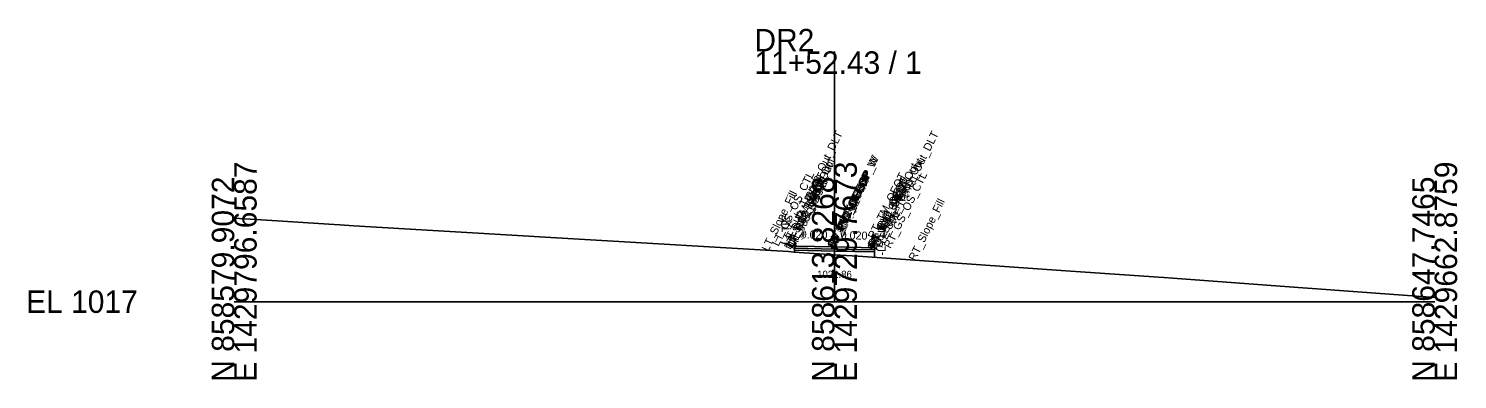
# Model space of a CAD drawing. Extents: x -26 to 1303, y -10 to 3033.
# Drawn here: x 1124.3 to 1302.8, y -9.7 to 34.1 of the extents above; entities that cross this region are included whole.
import ezdxf

# ---------------------------------------------------------------- set-up
doc = ezdxf.new("R2010")
doc.units = 0
for name, color, linetype in [('Exist Cross Section Cell', 7, 'Continuous'), ('Exist XS Center Line Elevation Label', 7, 'Continuous'), ('Exist XS Ground Line', 7, 'Continuous'), ('Prop CMT Pvmt Course 1', 7, 'Continuous'), ('Prop CMT Pvmt Course 2', 7, 'Continuous'), ('Prop CMT Pvmt Surface', 7, 'Continuous'), ('Prop CMT Pvmt Surface Overlay', 7, 'Continuous'), ('Prop CMT Shld Paved Course 1', 7, 'Continuous'), ('Prop CMT Shld Paved Course 2', 7, 'Continuous'), ('Prop CMT Slope Grass', 7, 'Continuous'), ('Prop CMT Subgrade Earthwork', 7, 'Continuous'), ('Prop XS Dump Level', 7, 'Continuous'), ('Prop XS EOT Tick Mark', 7, 'Continuous'), ('Prop XS SE Text', 7, 'Continuous'), ('Prop XSC Text', 7, 'Continuous')]:
    doc.layers.add(name, color=color, linetype=linetype)

msp = doc.modelspace()

# ---------------------------------------------------------------- linework, layer by layer
at = {"layer": 'Exist Cross Section Cell'}
for p, q in [((1225, 0), (1225, 31.22)), ((1150, 0), (1225, 0)), ((1225, 0), (1300, 0))]:
    msp.add_line(p, q, dxfattribs=at)
at = {"layer": 'Exist XS Ground Line'}
msp.add_lwpolyline([(1150, 10.41), (1156.02, 10.05), (1161.84, 9.67), (1163.21, 9.58), (1164.96, 9.46), (1186.81, 8.18), (1188.14, 8.1), (1192.41, 7.84), (1219.26, 6.24), (1219.97, 6.19), (1225, 5.86), (1226.48, 5.76), (1227.95, 5.66), (1253.9, 3.85), (1256.35, 3.67), (1265.5, 3.07), (1266.14, 3.02), (1267.3, 2.93), (1282.94, 1.75), (1284.68, 1.63), (1300, 0.52)], dxfattribs=at)
at = {"layer": 'Prop CMT Pvmt Course 1'}
for points in [[(1225, 6.82), (1220, 6.92)], [(1220, 6.92), (1220, 6.67)], [(1220, 6.67), (1225, 6.57)], [(1225, 6.69), (1225, 6.82)], [(1225, 6.82), (1230, 6.72)], [(1225, 6.69), (1225, 6.82)], [(1225, 6.57), (1225, 6.69), (1225, 6.69)], [(1225, 6.57), (1225, 6.69), (1225, 6.69)], [(1230, 6.47), (1225, 6.57)], [(1230, 6.72), (1230, 6.47)]]:
    msp.add_lwpolyline(points, dxfattribs=at)
at = {"layer": 'Prop CMT Pvmt Course 2'}
for points in [[(1225, 6.57), (1220, 6.67)], [(1220, 6.67), (1220, 6.42)], [(1220, 6.42), (1225, 6.32)], [(1225, 6.32), (1225, 6.57)], [(1225, 6.32), (1225, 6.57)], [(1225, 6.57), (1230, 6.47)], [(1230, 6.22), (1225, 6.32)], [(1230, 6.47), (1230, 6.22)]]:
    msp.add_lwpolyline(points, dxfattribs=at)
at = {"layer": 'Prop CMT Pvmt Surface'}
for points in [[(1225, 6.82), (1220, 6.92)], [(1225, 6.82), (1230, 6.72)]]:
    msp.add_lwpolyline(points, dxfattribs=at)
at = {"layer": 'Prop CMT Pvmt Surface Overlay'}
for points in [[(1225, 6.82), (1220, 6.92)], [(1225, 6.82), (1230, 6.72)]]:
    msp.add_lwpolyline(points, dxfattribs=at)
at = {"layer": 'Prop CMT Shld Paved Course 1'}
for points in [[(1220, 6.67), (1220, 6.92)], [(1230, 6.47), (1230, 6.72)]]:
    msp.add_lwpolyline(points, dxfattribs=at)
at = {"layer": 'Prop CMT Shld Paved Course 2'}
for points in [[(1220, 6.42), (1220, 6.67)], [(1230, 6.22), (1230, 6.47)]]:
    msp.add_lwpolyline(points, dxfattribs=at)
at = {"layer": 'Prop CMT Slope Grass'}
for p, q in [((1220, 6.42), (1220, 6.19)), ((1230, 6.22), (1230, 5.52))]:
    msp.add_line(p, q, dxfattribs=at)
at = {"layer": 'Prop CMT Subgrade Earthwork'}
for q in [(1220, 6.42), (1230, 6.22)]:
    msp.add_line((1225, 6.32), q, dxfattribs=at)
at = {"layer": 'Prop XS EOT Tick Mark'}
for points in [[(1220, 6.92), (1220, 7.92)], [(1230, 6.72), (1230, 7.72)]]:
    msp.add_lwpolyline(points, dxfattribs=at)

# ---------------------------------------------------------------- texts
at = {"layer": 'Exist Cross Section Cell'}
for s, p in [('DR2', (1215, 31.22)), ('11+52.43 / 1', (1215, 28.42)), ('EL 1017', (1124, -1.4))]:
    msp.add_text(s, height=2.8, dxfattribs=at).set_placement(p)
for s, p in [('E 1429796.6587', (1152.8, -10)), ('E 1429729.7673', (1227.8, -10)), ('E 1429662.8759', (1302.8, -10)), ('N 858579.9072', (1150, -10)), ('N 858613.8268', (1225, -10)), ('N 858647.7465', (1300, -10))]:
    msp.add_text(s, height=2.8, rotation=90, dxfattribs=at).set_placement(p)
at = {"layer": 'Exist XS Center Line Elevation Label'}
msp.add_text('1022.86', height=0.9, dxfattribs=at).set_placement((1222.83, 2.96))
at = {"layer": 'Prop XS Dump Level'}
for s, p in [('LT_Sub_Trench_Out_DLT', (1219.06, 6.88)), ('RT_Sub_Trench_Out_DLT', (1230.94, 6.64)), ('LT_Sub_Trench_Out', (1219.51, 6.43)), ('RT_PV1_OEEOP_W', (1225, 6.69)), ('LT_PV1_OEEOP_W', (1225, 6.69)), ('RT_Sub_Trench_Out', (1230.51, 6.21)), ('LT_PS2_Shelf_Out', (1219.75, 6.67)), ('LT_TM_OEOT', (1220, 7.92)), ('RT_PV2_OEEOP', (1225, 6.57)), ('LT_PV2_OEEOP', (1225, 6.57)), ('RT_TM_OEOT', (1230, 7.72)), ('RT_PS2_Shelf_Out', (1230.26, 6.46)), ('LT_GS_OS_CTL', (1218, 6.84)), ('LT_PS2_OEOP', (1219.75, 6.67)), ('LT_PV1_OEOT', (1220, 6.92)), ('LT_PV2_OEOT', (1220, 6.67)), ('LT_Sub_OEOT', (1220, 6.42)), ('RT_Sub_OEEOP', (1225, 6.32)), ('LT_Sub_OEEOP', (1225, 6.32)), ('RT_PV1_OEOT', (1230, 6.72)), ('RT_PV2_OEOT', (1230, 6.47)), ('RT_Sub_OEOT', (1230, 6.22)), ('RT_PS2_OEOP', (1230.26, 6.46)), ('RT_GS_OS_CTL', (1232, 6.56)), ('LT_Slope_Fill', (1216.73, 6.2)), ('PV1_PGL_W', (1225, 6.69)), ('RT_Slope_Fill', (1235.09, 5.01)), ('PV1_PGL', (1225, 6.82))]:
    msp.add_text(s, height=1, rotation=63.5833, dxfattribs=at).set_placement(p)
at = {"layer": 'Prop XS SE Text'}
for p in [(1220.77, 7.9), (1225.77, 7.8)]:
    msp.add_text('0.020', height=1, rotation=358.8542, dxfattribs=at).set_placement(p)
at = {"layer": 'Prop XSC Text'}
for p in [(1219.42, 6.67), (1231.38, 5.75)]:
    msp.add_text('-L- TIE', height=1, rotation=90, dxfattribs=at).set_placement(p)

doc.saveas('drawing.dxf')
